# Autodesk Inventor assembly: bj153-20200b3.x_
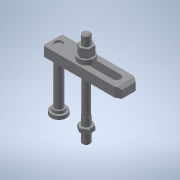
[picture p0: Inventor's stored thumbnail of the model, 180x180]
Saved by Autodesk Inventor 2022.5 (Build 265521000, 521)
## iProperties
Part Number: bj153-20200b3.x_
Material: 一般
Document SubType Name: Assembly
Designer: ImaoCorp
Sending System: SOLIDWORKS 2017-2017317
MC: AMD64
MC_MODEL: Intel64 Family 6 Model 60 Stepping 3, GenuineIntel
OS: Windows_NT
FRU: Parasolid Version 29.0, build 201,  4-17-2017
FORMAT: text
GUISE: transmit
KEY: bj153-20200b3
FILE: bj153-20200b3.x_t
DATE: Fri Mar 15 10:22:16 2019
Author: ImaoCorp
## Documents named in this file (6)
- X:\14_SW2022-Inv2022\00_全2023-1023新製品(TCC)まで\b\bj153-20200b3\BJ153-20200B3.iam
- X:\14_SW2022-Inv2022\00_全2023-1023新製品(TCC)まで\b\bj153-20200b3\bj153-20200b3_01.ipt
- X:\14_SW2022-Inv2022\00_全2023-1023新製品(TCC)まで\b\bj153-20200b3\bj153-20200b3_02.ipt
- X:\14_SW2022-Inv2022\00_全2023-1023新製品(TCC)まで\b\bj153-20200b3\bj153-20200b3_03.ipt
- X:\14_SW2022-Inv2022\00_全2023-1023新製品(TCC)まで\b\bj153-20200b3\bj153-20200b3_04.ipt
- X:\14_SW2022-Inv2022\00_全2023-1023新製品(TCC)まで\b\bj153-20200b3\bj153-20200b3_05.ipt
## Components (5 placed, 5 different names)
1. bj153-20200b3_01
2. bj153-20200b3_02
3. bj153-20200b3_03
4. bj153-20200b3_04
5. bj153-20200b3_05
